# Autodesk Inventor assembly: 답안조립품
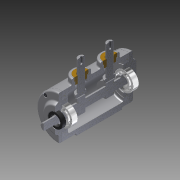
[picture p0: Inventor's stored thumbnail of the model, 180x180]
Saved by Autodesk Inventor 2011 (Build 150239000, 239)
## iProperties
Created: 2014-12
Part Number: 답안조립품
Document SubType Name: Assembly
Designer: user
Author: user
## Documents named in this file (10)
- D:\441225V1010\답안조립품.iam
- D:\441225V1010\1-본체.ipt
- D:\441225V1010\슬라이더.ipt
- D:\441225V1010\부시.ipt
- D:\441225V1010\2-축.ipt
- D:\441225V1010\베어링 6203.ipt
- D:\441225V1010\뒷커버.ipt
- D:\441225V1010\앞커버.ipt
- D:\441225V1010\오일실.ipt
- D:\441225V1010\M4-소켓머리.ipt
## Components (13 placed, 5 different names)
1. 1-본체:1
2. 2-축:1 — 각도:1
3. 7-베어링 6203:1
4. 7-베어링 6203:2
5. 8-오일실:1
6. 9-M4-소켓머리:1
7. 9-M4-소켓머리:2
8. 9-M4-소켓머리:3
9. 9-M4-소켓머리:4
10. 9-M4-소켓머리:5
11. 9-M4-소켓머리:6
12. 9-M4-소켓머리:7
13. 9-M4-소켓머리:8
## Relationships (1: Angle 1)
- 각도:1 [Angle]: 2-축:1
